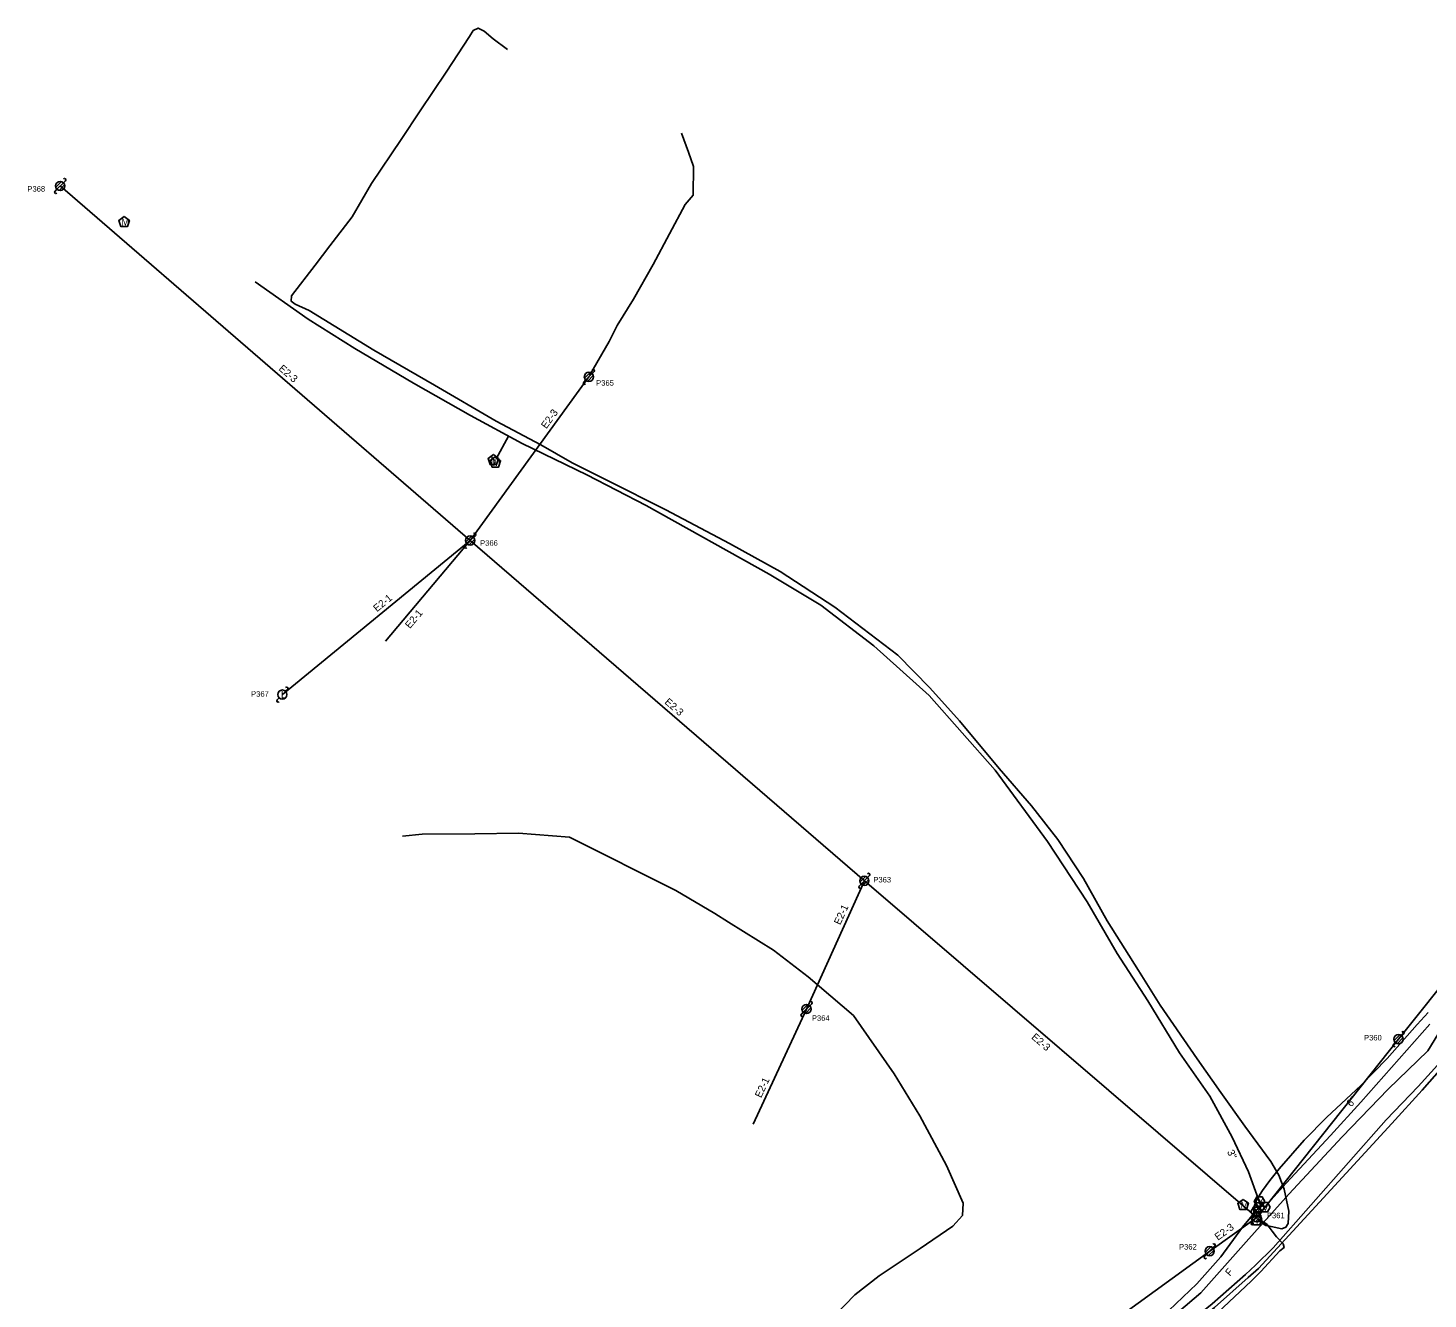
# Model space of a CAD drawing. Extents: x 1741604 to 1825760, y 1164229 to 1194908.
# Drawn here: x 1818924 to 1819688, y 1192978 to 1193671 of the extents above; entities that cross this region are included whole.
import ezdxf

# ---------------------------------------------------------------- set-up
doc = ezdxf.new("R2010")
doc.units = 0
for name, color, linetype in [('RD_EX_SU_Elec', 7, 'Continuous'), ('RD_EX_SU_H2O', 7, 'Continuous'), ('RD_EX_SU_Ovhd', 7, 'Continuous'), ('RD_EX_SU_Pole', 7, 'Continuous'), ('RD_EX_SU_Telecom', 7, 'Continuous'), ('RD_EX_SU_TX_H2O', 7, 'Continuous'), ('RD_EX_SU_TX_Pole', 7, 'Continuous'), ('RD_EX_SU_TX_Telecom', 7, 'Continuous')]:
    doc.layers.add(name, color=color, linetype=linetype)

# ---------------------------------------------------------------- blocks, each defined once
blk = doc.blocks.new('SUE_TPP')
at = {"layer": 'RD_EX_SU_Telecom'}
blk.add_lwpolyline([(0, 3), (-2.85, 0.93), (-1.76, -2.43), (1.76, -2.43), (2.85, 0.93)], close=True, dxfattribs=at)
blk.add_text('T', height=3.75, dxfattribs=at).set_placement((-1.25, -1.88))
blk = doc.blocks.new('SUE_WV')
at = {"layer": 'RD_EX_SU_H2O'}
blk.add_lwpolyline([(2.89, 0), (1.44, 2.5), (-1.44, 2.5), (-2.89, 0), (-1.44, -2.5), (1.44, -2.5)], close=True, dxfattribs=at)
blk.add_text('V', height=3.75, dxfattribs=at).set_placement((-1.43, -1.88))
blk = doc.blocks.new('SUE_PP')
at = {"layer": 'RD_EX_SU_Pole'}
for p, q in [((-2.41, -0.65), (0.65, 2.41)), ((-1.77, -1.77), (1.77, 1.77)), ((-0.65, -2.41), (2.41, 0.65)), ((1.77, 1.77), (2.83, 2.83)), ((-2.83, -2.83), (-1.77, -1.77))]:
    blk.add_line(p, q, dxfattribs=at)
blk.add_circle((0, 0), 2.5, dxfattribs=at)
for centre, start, end in [((2.3, 3.36), 315, 135), ((-2.3, -3.36), 135, 315)]:
    blk.add_arc(centre, 0.75, start, end, dxfattribs=at)
blk = doc.blocks.new('SUE_WM')
at = {"layer": 'RD_EX_SU_H2O'}
blk.add_lwpolyline([(0, 3.05), (-2.9, 0.94), (-1.79, -2.47), (1.79, -2.47), (2.9, 0.94)], close=True, dxfattribs=at)
blk.add_text('M', height=3.75, dxfattribs=at).set_placement((-1.43, -1.88))

msp = doc.modelspace()

# ---------------------------------------------------------------- linework, layer by layer
at = {"layer": 'RD_EX_SU_Elec'}
msp.add_lwpolyline([(1819230.6, 1193481.67), (1819241.34, 1193500.26), (1819245.73, 1193509.04), (1819254.55, 1193523.29), (1819265.34, 1193542.36), (1819274.25, 1193559.06), (1819282.74, 1193574.97), (1819287.14, 1193580.19), (1819287.28, 1193595.82), (1819284.62, 1193603.58), (1819280.7, 1193613.92)], dxfattribs=at)
at = {"layer": 'RD_EX_SU_H2O'}
msp.add_line((1819179.69, 1193436.17), (1819186.39, 1193448.66), dxfattribs=at)
for points in [[(1819048.07, 1193532.88), (1819077.09, 1193512.5), (1819102.46, 1193496.44), (1819134.46, 1193477.58), (1819165.58, 1193459.82), (1819193.84, 1193444.66), (1819229.04, 1193427.49), (1819261.39, 1193410.68), (1819328.67, 1193373.28), (1819356.81, 1193356.47), (1819385.78, 1193334.24), (1819415.84, 1193307.13), (1819451.95, 1193266.32), (1819480.52, 1193227.41), (1819502.02, 1193194.51), (1819518.53, 1193166.32), (1819535.12, 1193140.49), (1819552.45, 1193112.15), (1819569.12, 1193088.38), (1819581.22, 1193066.04), (1819590.07, 1193047.12), (1819595.46, 1193032.7), (1819596.79, 1193030.1), (1819598.5, 1193028.06)], [(1819599.25, 1193028.22), (1819610.67, 1193040.9), (1819634.92, 1193067.04), (1819651.37, 1193085.11), (1819672.34, 1193108.82), (1819688.99, 1193127.8)], [(1819345.55, 1192839.38), (1819376.57, 1192854.45), (1819389.99, 1192860.1), (1819409.3, 1192866.49), (1819438.97, 1192887.96), (1819460.47, 1192902.87), (1819483.57, 1192919.09), (1819502.68, 1192934.89), (1819526.07, 1192953.26), (1819546.69, 1192971.49), (1819561.98, 1192986.03), (1819575, 1193000.7), (1819586.85, 1193016.96), (1819595.57, 1193027.51), (1819597.59, 1193029.14)]]:
    msp.add_lwpolyline(points, dxfattribs=at)
at = {"layer": 'RD_EX_SU_Ovhd'}
for p, q in [((1818941.73, 1193585.12), (1819165.45, 1193391.65)), ((1819165.45, 1193391.65), (1819230.22, 1193480.98)), ((1819062.98, 1193307.6), (1819165.45, 1193391.65)), ((1819119.23, 1193336.8), (1819165.45, 1193391.65)), ((1819165.45, 1193391.65), (1819380.54, 1193205.96)), ((1819672.01, 1193119.56), (1819796.18, 1193275.62)), ((1819348.97, 1193135.99), (1819380.54, 1193205.96)), ((1819380.54, 1193205.96), (1819594.6, 1193022.31)), ((1819319.9, 1193073.22), (1819348.97, 1193135.99)), ((1819594.6, 1193022.31), (1819672.01, 1193119.56)), ((1819568.97, 1193003.85), (1819594.6, 1193022.31)), ((1819360.95, 1192853.26), (1819568.97, 1193003.85))]:
    msp.add_line(p, q, dxfattribs=at)
at = {"layer": 'RD_EX_SU_Pole'}
for p, q in [((1819060.15, 1193304.77), (1819061.21, 1193305.83)), ((1819064.75, 1193309.37), (1819065.81, 1193310.43)), ((1819669.6, 1193118.92), (1819672.66, 1193121.98)), ((1819670.25, 1193117.8), (1819673.78, 1193121.33)), ((1819671.37, 1193117.15), (1819674.43, 1193120.21)), ((1819673.78, 1193121.33), (1819674.84, 1193122.39)), ((1819669.19, 1193116.73), (1819670.25, 1193117.8)), ((1819592.19, 1193021.67), (1819595.25, 1193024.73)), ((1819592.83, 1193020.55), (1819596.37, 1193024.08)), ((1819593.95, 1193019.9), (1819597.01, 1193022.96)), ((1819596.37, 1193024.08), (1819597.43, 1193025.14)), ((1819591.77, 1193019.49), (1819592.83, 1193020.55)), ((1819566.56, 1193003.21), (1819569.62, 1193006.27)), ((1819567.21, 1193002.09), (1819570.74, 1193005.62)), ((1819570.74, 1193005.62), (1819571.8, 1193006.68)), ((1819566.15, 1193001.03), (1819567.21, 1193002.09)), ((1819568.33, 1193001.44), (1819571.39, 1193004.5))]:
    msp.add_line(p, q, dxfattribs=at)
for centre in [(1819062.98, 1193307.6), (1819672.01, 1193119.56), (1819594.6, 1193022.31), (1819568.97, 1193003.85)]:
    msp.add_circle(centre, 2.5, dxfattribs=at)
for centre, start, end in [((1819065.28, 1193310.96), 315, 135), ((1819060.68, 1193304.24), 135, 315), ((1819674.31, 1193122.92), 315, 135), ((1819669.72, 1193116.2), 135, 315), ((1819596.9, 1193025.67), 315, 135), ((1819592.3, 1193018.96), 135, 315), ((1819571.27, 1193007.21), 315, 135), ((1819566.68, 1193000.5), 135, 315)]:
    msp.add_arc(centre, 0.75, start, end, dxfattribs=at)
at = {"layer": 'RD_EX_SU_Telecom'}
msp.add_line((1819595.63, 1192994.37), (1819668.3, 1193073.59), dxfattribs=at)
for points in [[(1819165.1, 1193666.68), (1819167.02, 1193669.89), (1819169.79, 1193671.33), (1819173.12, 1193669.61), (1819177.92, 1193665.5), (1819185.81, 1193659.55)], [(1819165.1, 1193666.68), (1819152.27, 1193647.27), (1819138.16, 1193626.13), (1819127.74, 1193610.48), (1819111.66, 1193586.5), (1819101.05, 1193568.31), (1819088.86, 1193552.38), (1819080.84, 1193541.9), (1819067.93, 1193525.2), (1819067.8, 1193522.23), (1819069.92, 1193520.65), (1819077.57, 1193517.13), (1819112.89, 1193495.47), (1819146.03, 1193476.5), (1819179.69, 1193456.73), (1819204.03, 1193443.92), (1819221.16, 1193434.03), (1819240.31, 1193424.49), (1819272.16, 1193408.47), (1819306.98, 1193390.11), (1819334.57, 1193374.69), (1819364.37, 1193355.37), (1819398.7, 1193329.16), (1819416.19, 1193311.3)], [(1819416.19, 1193311.3), (1819432.47, 1193293.18), (1819454.01, 1193267.32), (1819471.73, 1193246.89), (1819486.05, 1193228.45), (1819500.13, 1193207.2), (1819513.04, 1193184.2), (1819530.06, 1193156.98), (1819541.96, 1193138.15), (1819562.06, 1193108.85), (1819574.98, 1193090.46), (1819588.05, 1193072.12), (1819602.41, 1193052.78), (1819606.73, 1193045.27), (1819609.66, 1193037.68), (1819612.08, 1193025.62), (1819611.73, 1193018.9), (1819610.57, 1193016.98), (1819608.37, 1193015.99), (1819602.44, 1193017.32), (1819599.63, 1193017.97), (1819595.45, 1193020.67)], [(1819128.48, 1193230.36), (1819139.23, 1193231.36), (1819167.89, 1193231.69), (1819191.73, 1193231.93), (1819219.56, 1193229.8), (1819277.68, 1193200.71), (1819298.98, 1193188.07), (1819306.48, 1193183.44), (1819330.91, 1193168.07), (1819349.8, 1193153.65), (1819374.54, 1193132.49), (1819396.83, 1193100.65), (1819410.75, 1193077.72), (1819425.34, 1193050.68), (1819434.48, 1193030.11), (1819434.05, 1193023.32), (1819428.87, 1193017.55), (1819410.93, 1193005.38), (1819388.53, 1192990.35), (1819375.28, 1192980.06), (1819364.45, 1192968.69), (1819356.15, 1192960.22), (1819346.63, 1192956.31), (1819339.77, 1192955.45)], [(1819534.78, 1192956.25), (1819564.18, 1192981.19), (1819590.31, 1193010.68), (1819612.11, 1193035.05), (1819641.17, 1193066.18), (1819666.35, 1193092.21), (1819687.97, 1193113.27), (1819702.39, 1193136.72)], [(1819593.96, 1193022), (1819593.01, 1193024.01), (1819593.06, 1193027.85), (1819594.77, 1193032.07), (1819597.79, 1193036.95), (1819601.75, 1193042.41), (1819606.9, 1193048.81), (1819620.51, 1193064.51), (1819632.93, 1193076.93), (1819651.49, 1193094.19), (1819665.88, 1193109.02), (1819682.17, 1193127.52), (1819688.26, 1193134.2)], [(1819665.19, 1193075.46), (1819682.72, 1193093.75), (1819700.3, 1193113.15)], [(1819668.3, 1193073.59), (1819684.89, 1193091.68), (1819702.27, 1193111.57)], [(1819364.03, 1192854.37), (1819381.2, 1192862.37), (1819394.91, 1192867.85), (1819407.79, 1192874.27), (1819427.23, 1192884.85), (1819457.09, 1192900), (1819476.86, 1192908.22), (1819493.97, 1192914.94), (1819521.17, 1192936.21), (1819549.02, 1192957.78), (1819570.26, 1192975.07), (1819588.56, 1192991.14), (1819593.92, 1192996.29), (1819603.54, 1193005.74), (1819665.19, 1193075.46)], [(1819607.23, 1193004.1), (1819609.56, 1193005.84), (1819608.98, 1193007.87), (1819605.45, 1193011.76), (1819603.02, 1193014.75), (1819600.26, 1193018.37), (1819597.44, 1193020.36), (1819595.52, 1193021.08)], [(1819364.11, 1192852.09), (1819364.72, 1192850.69), (1819369.27, 1192842.18), (1819372.64, 1192837.47), (1819375.87, 1192835.53), (1819380.49, 1192837.86), (1819395.91, 1192845.17), (1819415.93, 1192856.22), (1819436.36, 1192867.95), (1819464.92, 1192886.85), (1819483.14, 1192899.03), (1819497.16, 1192909.11), (1819525.1, 1192930.33), (1819552.8, 1192952.61), (1819573.37, 1192970.32), (1819591.5, 1192987.56), (1819596.93, 1192992.76), (1819607.23, 1193004.1)], [(1819365.05, 1192853.82), (1819381.66, 1192860.65), (1819395.31, 1192866.85), (1819402.61, 1192865.78), (1819412.38, 1192861.93), (1819418.71, 1192862.32), (1819434.68, 1192871.75), (1819463.69, 1192889.06), (1819481.34, 1192902.11), (1819495.32, 1192912.17), (1819522.98, 1192933.84), (1819550.54, 1192955.45), (1819571.53, 1192973.06), (1819590, 1192989.44), (1819595.63, 1192994.37)]]:
    msp.add_lwpolyline(points, dxfattribs=at)

# ---------------------------------------------------------------- block references
at = {"layer": 'RD_EX_SU_H2O'}
for name, p in [('SUE_WM', (1818976.61, 1193565.42)), ('SUE_WM', (1819178.08, 1193435.53)), ('SUE_WM', (1819179.14, 1193434.21)), ('SUE_WM', (1819587.2, 1193029.05)), ('SUE_WV', (1819595.99, 1193027.83)), ('SUE_WV', (1819596.16, 1193030.94)), ('SUE_WV', (1819599.1, 1193027.86)), ('SUE_WV', (1819594.37, 1193025.39))]:
    msp.add_blockref(name, p, dxfattribs=at)
at = {"layer": 'RD_EX_SU_Pole'}
for p in [(1818941.73, 1193585.12), (1819230.22, 1193480.98), (1819165.45, 1193391.65), (1819380.54, 1193205.96), (1819348.97, 1193135.99)]:
    msp.add_blockref('SUE_PP', p, dxfattribs=at)
at = {"layer": 'RD_EX_SU_Telecom'}
msp.add_blockref('SUE_TPP', (1819594.62, 1193020.76), dxfattribs=at)

# ---------------------------------------------------------------- texts
at = {"layer": 'RD_EX_SU_Ovhd'}
for s, rotation, p in [('E2-3', 319.14605, (1819060.63, 1193484.94)), ('E2-3', 54.05312, (1819206.99, 1193452.34)), ('E2-1', 39.35995, (1819114.56, 1193352.49)), ('E2-1', 49.88006, (1819132.55, 1193343.29)), ('E2-3', 319.19594, (1819271.17, 1193303.02)), ('E2-1', 65.71755, (1819367.36, 1193181.61)), ('E2-3', 319.37377, (1819471.35, 1193120.15)), ('E2-1', 65.14772, (1819324.19, 1193087.25)), ('E2-3', 35.76798, (1819573.44, 1193009.54))]:
    msp.add_text(s, height=4, rotation=rotation, dxfattribs=at).set_placement(p)
at = {"layer": 'RD_EX_SU_Pole'}
msp.add_text('L', height=4, dxfattribs=at).set_placement((1819062.12, 1193305.6))
at = {"layer": 'RD_EX_SU_TX_H2O'}
for s, rotation, p in [('6"', 47.69422, (1819646.14, 1193082.33)), ('3"', 295.07792, (1819578.31, 1193058.1))]:
    msp.add_text(s, height=4, rotation=rotation, dxfattribs=at).set_placement(p)
at = {"layer": 'RD_EX_SU_TX_Pole'}
for s, p in [('P368', (1818923.83, 1193582.03)), ('P365', (1819234.17, 1193476.17)), ('P366', (1819170.85, 1193388.8)), ('P367', (1819045.89, 1193306.44)), ('P363', (1819385.43, 1193205.08)), ('P364', (1819351.89, 1193129.58)), ('P360', (1819653.18, 1193118.87)), ('P361', (1819600.21, 1193021.86)), ('P362', (1819552.23, 1193004.75))]:
    msp.add_text(s, height=3, dxfattribs=at).set_placement(p)
at = {"layer": 'RD_EX_SU_TX_Telecom'}
msp.add_text('F', height=4, rotation=48.46278, dxfattribs=at).set_placement((1819579.96, 1192989.95))

doc.saveas('drawing.dxf')
